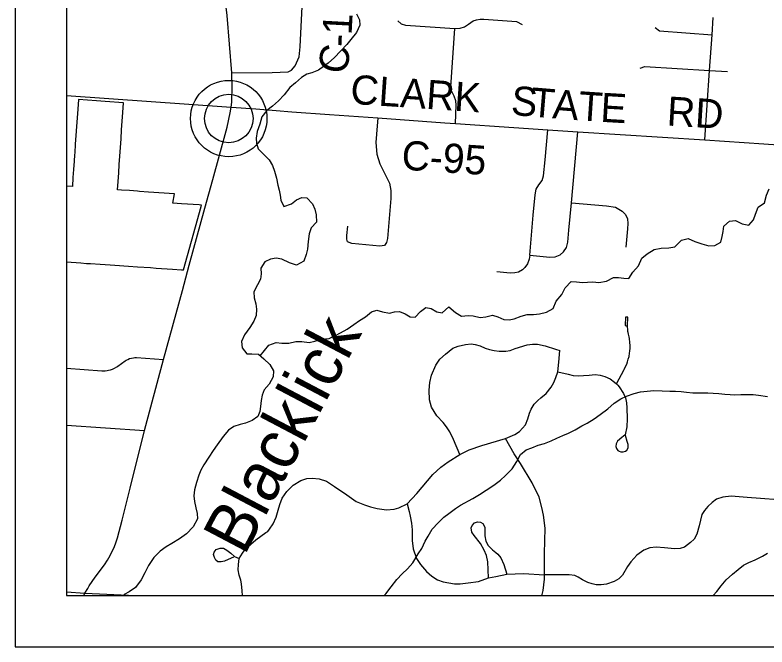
# Model space of a CAD drawing. Extents: x 0 to 91.3, y -0.7 to 22.
# Drawn here: x 2 to 3.464, y 14 to 15.231 of the extents above; entities that cross this region are included whole.
import ezdxf

# ---------------------------------------------------------------- set-up
doc = ezdxf.new("R2010")
doc.units = 0
for name, color, linetype in [('GM_X_Corporation', 7, 'Continuous'), ('GM_X_County_Road', 7, 'Continuous'), ('GM_X_County_Road_Text', 7, 'Continuous'), ('GM_X_Minor_River', 7, 'Continuous'), ('GM_X_Minor_River_Text', 7, 'Continuous'), ('GM_X_Township_Road', 7, 'Continuous'), ('GM_X_Unincorporated', 7, 'Continuous'), ('GM_X_Unincorporated_Location', 7, 'Continuous'), ('SH_Data', 7, 'Continuous')]:
    doc.layers.add(name, color=color, linetype=linetype)

msp = doc.modelspace()

# ---------------------------------------------------------------- linework, layer by layer
at = {"layer": 'GM_X_Corporation'}
msp.add_lwpolyline([(2.1, 20.8844), (2.1, 14.1), (4.5273, 14.1), (4.5361, 14.2234), (4.5616, 14.5843), (4.5901, 15.0403), (4.6027, 15.2253), (4.6241, 15.5494), (4.624, 15.5538), (4.6966, 16.7952), (4.7039, 16.921), (4.7369, 17.4842), (4.7381, 17.5094), (4.7391, 17.5254), (4.7562, 17.8002), (4.7688, 17.9561), (4.7799, 18.0944), (4.7833, 18.1361), (4.8242, 18.6326)], dxfattribs=at)
for points in [[(2.1, 15.7138), (2.1, 14.1), (4.5273, 14.1), (4.5361, 14.2234), (4.5616, 14.5843), (4.5901, 15.0403), (4.6027, 15.2253), (4.6241, 15.5494), (4.1118, 15.5861), (3.7652, 15.6088), (3.1007, 15.6507), (2.7426, 15.6727), (2.3611, 15.6969)], [(2.1, 14.8978), (2.1, 14.7499), (2.1282, 14.748), (2.1393, 14.7473), (2.1471, 14.7468), (2.166, 14.7455), (2.1849, 14.7442), (2.1944, 14.7436), (2.2208, 14.7418), (2.2386, 14.7406), (2.2637, 14.7389), (2.275, 14.7382), (2.3068, 14.736), (2.3242, 14.7349), (2.3281, 14.7346), (2.359, 14.8462), (2.3629, 14.8607), (2.3587, 14.861), (2.3239, 14.8634), (2.3072, 14.8645), (2.3102, 14.8825), (2.2599, 14.8862), (2.2423, 14.8875), (2.2386, 14.8877), (2.223, 14.8889), (2.2072, 14.89), (2.1994, 14.8906), (2.2006, 14.9069), (2.2017, 14.9239), (2.2029, 14.94), (2.204, 14.956), (2.2051, 14.973), (2.2063, 14.99), (2.2075, 15.0071), (2.2086, 15.0241), (2.2098, 15.0411), (2.2111, 15.06), (2.1757, 15.0626), (2.1587, 15.0639), (2.1233, 15.0665), (2.122, 15.0476), (2.1208, 15.0306), (2.1197, 15.0136), (2.1185, 14.9966), (2.1173, 14.9796), (2.1161, 14.9626), (2.1159, 14.9587), (2.115, 14.9465), (2.1139, 14.9304), (2.1128, 14.9144), (2.1116, 14.8969)]]:
    msp.add_lwpolyline(points, close=True, dxfattribs=at)
at = {"layer": 'GM_X_County_Road'}
msp.add_line((2.1, 15.0745), (2.4208, 15.0514), dxfattribs=at)
for points in [[(2.4217, 15.1187), (2.413, 15.2298), (2.3896, 15.4238), (2.3677, 15.6299), (2.3614, 15.6963)], [(2.4217, 15.1187), (2.5005, 15.1191), (2.5317, 15.1201), (2.5384, 15.1237), (2.5452, 15.1323), (2.5529, 15.1498), (2.5547, 15.1688), (2.5697, 15.4694)], [(2.4208, 15.0514), (2.4219, 15.0611), (2.4221, 15.0671), (2.4229, 15.088), (2.4217, 15.1187)], [(2.2522, 14.4216), (2.2887, 14.5597), (2.3258, 14.6947), (2.3388, 14.7436), (2.3695, 14.8547), (2.3849, 14.9109), (2.4127, 15.0126), (2.4189, 15.0403), (2.4208, 15.0514)], [(2.4208, 15.0514), (2.4687, 15.048), (2.508, 15.0447), (2.5387, 15.0425)], [(2.5387, 15.0425), (2.6121, 15.0373), (2.706, 15.0307), (2.8364, 15.0213), (2.8571, 15.0199), (2.971, 15.012), (3.0369, 15.0072), (3.0952, 15.0032), (3.3423, 14.9878), (3.4576, 14.9802), (3.5594, 14.9727)], [(2.1341, 14.1), (2.1361, 14.1049), (2.1414, 14.114), (2.1444, 14.1191), (2.1501, 14.1278), (2.156, 14.1357), (2.174, 14.16), (2.1802, 14.1694), (2.1851, 14.1781), (2.1934, 14.1954), (2.1963, 14.2029), (2.1994, 14.2127), (2.2086, 14.2467), (2.2241, 14.3094), (2.2522, 14.4216)]]:
    msp.add_lwpolyline(points, dxfattribs=at)
at = {"layer": 'GM_X_Minor_River'}
for points in [[(2.6645, 15.2332), (2.6705, 15.2218), (2.6708, 15.2115), (2.6647, 15.1971), (2.6536, 15.1835), (2.6455, 15.1733), (2.6333, 15.1609), (2.6215, 15.1484), (2.6096, 15.1375), (2.6001, 15.1307), (2.5906, 15.1236), (2.5776, 15.1187), (2.5677, 15.1161), (2.5575, 15.1094), (2.5456, 15.0988), (2.5349, 15.0901), (2.5235, 15.0754), (2.5128, 15.0641), (2.5013, 15.0535), (2.4903, 15.0449), (2.4803, 15.0328), (2.4764, 15.0184), (2.4714, 15.0044), (2.4694, 14.9911), (2.4701, 14.9816), (2.4735, 14.9706), (2.4821, 14.961), (2.4946, 14.9488), (2.5013, 14.9378), (2.5051, 14.9267), (2.5092, 14.9131), (2.5117, 14.8994), (2.514, 14.8895), (2.5158, 14.88), (2.5176, 14.8701), (2.5232, 14.8579), (2.5381, 14.8635), (2.5476, 14.8707), (2.5579, 14.8756), (2.5678, 14.8751), (2.5791, 14.8633), (2.5832, 14.8526), (2.5858, 14.842), (2.5868, 14.8276), (2.5765, 14.8166), (2.5726, 14.8049), (2.5703, 14.7897), (2.569, 14.7749), (2.5667, 14.7643), (2.562, 14.7514), (2.548, 14.7439), (2.5343, 14.7482), (2.5196, 14.7551), (2.5082, 14.7571), (2.4972, 14.7552), (2.4865, 14.75), (2.4785, 14.7379), (2.4788, 14.7269), (2.4779, 14.7163), (2.4718, 14.7057), (2.4645, 14.6921), (2.4656, 14.6799), (2.4685, 14.6685)], [(2.4771, 14.5674), (2.4942, 14.5879), (2.5083, 14.5928), (2.5193, 14.5919), (2.533, 14.5918), (2.5467, 14.5952), (2.558, 14.5951), (2.5728, 14.5931), (2.5838, 14.5957), (2.5964, 14.5994), (2.6112, 14.6012), (2.6238, 14.6065), (2.6337, 14.6117), (2.6462, 14.6192), (2.6592, 14.6279), (2.6706, 14.6358), (2.6824, 14.6429), (2.6935, 14.6527), (2.7042, 14.6561), (2.7155, 14.653), (2.7288, 14.6502), (2.7383, 14.6528), (2.7486, 14.6532), (2.7592, 14.6489), (2.769, 14.6428), (2.7785, 14.6424), (2.7892, 14.6533), (2.7995, 14.6612), (2.8097, 14.6596), (2.821, 14.6527), (2.8313, 14.6508), (2.8443, 14.6625), (2.8571, 14.6518), (2.8692, 14.6445), (2.8821, 14.6455), (2.8916, 14.6451), (2.9052, 14.642), (2.9162, 14.6434), (2.9292, 14.6464), (2.9394, 14.6433), (2.9511, 14.6379), (2.9618, 14.6371), (2.9713, 14.6389), (2.9853, 14.6442), (2.9971, 14.6475), (3.0093, 14.6478), (3.021, 14.6489), (3.0347, 14.6522), (3.0473, 14.6593), (3.0531, 14.6733), (3.0645, 14.6866), (3.0707, 14.6994), (3.0822, 14.7119), (3.0928, 14.7114), (3.1042, 14.7102), (3.1144, 14.7109), (3.1243, 14.7112), (3.1364, 14.71), (3.1512, 14.7126), (3.1646, 14.7197), (3.1748, 14.7197), (3.1847, 14.7181), (3.1945, 14.7177), (3.2026, 14.7301), (3.2133, 14.7426), (3.2202, 14.7574), (3.2301, 14.7656), (3.2442, 14.7743), (3.2579, 14.7769), (3.2727, 14.7775), (3.2841, 14.7797), (3.2975, 14.7922), (3.3104, 14.7955), (3.3233, 14.7898), (3.3365, 14.7851), (3.3502, 14.7816), (3.3619, 14.7823), (3.3737, 14.7883), (3.3765, 14.7993), (3.378, 14.8095), (3.3796, 14.8194), (3.3903, 14.8292), (3.4021, 14.8307), (3.4153, 14.8245), (3.4282, 14.8214), (3.4374, 14.8323), (3.4409, 14.8429), (3.4463, 14.8566), (3.4585, 14.8652), (3.4624, 14.8804), (3.4681, 14.8925)], [(2.4685, 14.6685), (2.47, 14.6583), (2.4692, 14.6454), (2.4645, 14.6344), (2.4569, 14.6223), (2.4469, 14.6083), (2.4408, 14.5951), (2.4418, 14.5825), (2.4512, 14.5707), (2.4607, 14.5707), (2.474, 14.5702), (2.4842, 14.561), (2.4959, 14.5503), (2.503, 14.5378), (2.5026, 14.526), (2.4945, 14.512), (2.485, 14.5007), (2.4807, 14.4908), (2.4791, 14.4798), (2.4775, 14.4685), (2.4763, 14.459), (2.4725, 14.4491), (2.4614, 14.4412), (2.4485, 14.436), (2.4382, 14.4334), (2.4261, 14.4293), (2.4158, 14.4225), (2.4051, 14.4097), (2.3936, 14.3935), (2.3859, 14.3829), (2.3771, 14.37), (2.3675, 14.3545), (2.3618, 14.3443), (2.3575, 14.3345), (2.3529, 14.3201), (2.3494, 14.3061), (2.3482, 14.2947), (2.3492, 14.2833), (2.3518, 14.2711), (2.3548, 14.2597), (2.3551, 14.2499), (2.3466, 14.234), (2.334, 14.2204), (2.3199, 14.2106), (2.3051, 14.2016), (2.2944, 14.1948), (2.2826, 14.1865), (2.27, 14.1745), (2.2596, 14.1586), (2.2527, 14.1442), (2.2454, 14.1306), (2.2347, 14.1159), (2.2221, 14.1072), (2.2126, 14.102), (2.2116, 14.1)], [(2.7187, 14.1), (2.722, 14.1034), (2.7319, 14.117), (2.743, 14.1314), (2.7533, 14.1427), (2.764, 14.1521), (2.7743, 14.1638), (2.7847, 14.1816), (2.792, 14.1918), (2.7981, 14.2058), (2.8039, 14.2156), (2.8119, 14.2293), (2.8234, 14.2421), (2.8345, 14.2527), (2.8444, 14.2602), (2.857, 14.27), (2.8669, 14.276), (2.8913, 14.2895), (2.9042, 14.297), (2.9172, 14.3053), (2.9317, 14.3151), (2.9446, 14.3252), (2.9545, 14.3339), (2.9679, 14.3471), (2.9767, 14.3611), (2.984, 14.3751), (2.9951, 14.3838), (3.0061, 14.3882), (3.0183, 14.3931), (3.0308, 14.3961), (3.0434, 14.4013), (3.0544, 14.4065), (3.0659, 14.4118), (3.0773, 14.4167), (3.0902, 14.423), (3.1032, 14.4309), (3.1135, 14.4362), (3.1275, 14.4444), (3.139, 14.4527), (3.1539, 14.464), (3.1664, 14.4746), (3.1794, 14.4832), (3.1904, 14.4885), (3.2053, 14.4937), (3.2174, 14.4967), (3.2304, 14.4981), (3.2436, 14.4995), (3.2596, 14.4991)], [(3.2596, 14.4991), (3.2748, 14.4986), (3.2854, 14.4981), (3.2968, 14.4977), (3.3066, 14.4965), (3.3195, 14.4953), (3.329, 14.4948), (3.3389, 14.4952), (3.3484, 14.4951), (3.3586, 14.4947), (3.3696, 14.4938), (3.3818, 14.4923), (3.3916, 14.4918), (3.4011, 14.4914), (3.4129, 14.4917), (3.4239, 14.492), (3.4368, 14.4915), (3.447, 14.4907), (3.4645, 14.488)], [(3.3585, 14.1), (3.3657, 14.1083), (3.3745, 14.1192), (3.3844, 14.1306), (3.3966, 14.1415), (3.4073, 14.1506), (3.4176, 14.1592), (3.4283, 14.1645), (3.4408, 14.1697), (3.4549, 14.1772), (3.4645, 14.1825)]]:
    msp.add_lwpolyline(points, dxfattribs=at)
at = {"layer": 'GM_X_Township_Road'}
for p, q in [((3.3516, 15.1232), (3.387, 15.1209)), ((2.1, 14.4321), (2.2522, 14.4216)), ((2.1, 14.1072), (2.1361, 14.1049)), ((2.1361, 14.1049), (2.2351, 14.1))]:
    msp.add_line(p, q, dxfattribs=at)
for points in [[(2.856, 15.2048), (2.8661, 15.2051), (2.8746, 15.2079), (2.8829, 15.213), (2.8919, 15.2194), (2.8985, 15.2217), (2.905, 15.2227), (2.9126, 15.2227), (2.9761, 15.2186), (2.9872, 15.2127)], [(3.3423, 14.9878), (3.3516, 15.1232), (3.3568, 15.1925), (3.3586, 15.2262)], [(2.7448, 15.2197), (2.7513, 15.2138), (2.7602, 15.2112), (2.856, 15.2048)], [(3.246, 15.2067), (3.2545, 15.2003), (3.3568, 15.1925)], [(2.8571, 15.0199), (2.8588, 15.0557), (2.8579, 15.0639), (2.8546, 15.0731), (2.8493, 15.0836), (2.8483, 15.0908), (2.856, 15.2048)], [(3.2167, 15.1276), (3.2256, 15.1309), (3.3516, 15.1232)], [(2.706, 15.0307), (2.7038, 14.999), (2.7025, 14.9827), (2.7043, 14.96), (2.7103, 14.9414), (2.7289, 14.9037), (2.7312, 14.8889), (2.7316, 14.8734), (2.7251, 14.7955), (2.7231, 14.7879), (2.719, 14.7823), (2.7101, 14.7807), (2.6557, 14.7858), (2.6472, 14.7895), (2.6459, 14.7946), (2.6459, 14.8014), (2.6478, 14.82)], [(3.0019, 14.7629), (3.0087, 14.8409), (3.0121, 14.8805), (3.0142, 14.8918), (3.0194, 14.9005), (3.0257, 14.9085), (3.0287, 14.9178), (3.0316, 14.9489), (3.0369, 15.0072)], [(3.0019, 14.7629), (3.0407, 14.7591), (3.0511, 14.7598), (3.0611, 14.764), (3.0676, 14.7694), (3.0734, 14.7782), (3.0762, 14.7886), (3.078, 14.812), (3.0831, 14.8651), (3.0952, 15.0032)], [(3.0831, 14.8651), (3.151, 14.859), (3.1687, 14.8565), (3.1817, 14.8492), (3.1885, 14.8423), (3.1918, 14.834), (3.1927, 14.8251), (3.1922, 14.8146), (3.1889, 14.7785)], [(3.0019, 14.7629), (3.0007, 14.7552), (2.9976, 14.7462), (2.9925, 14.7389), (2.9879, 14.7344), (2.9799, 14.7303), (2.9727, 14.7287), (2.9635, 14.7284), (2.938, 14.7306)], [(3.1707, 14.5123), (3.1856, 14.5402), (3.1864, 14.5419), (3.1885, 14.5461), (3.1906, 14.551), (3.1922, 14.5556), (3.1937, 14.5605), (3.195, 14.5657), (3.1961, 14.5722), (3.1966, 14.5764), (3.197, 14.5822), (3.197, 14.5882), (3.1967, 14.5927), (3.1965, 14.5955), (3.1961, 14.5986), (3.1957, 14.6012), (3.1951, 14.6041), (3.1945, 14.6069), (3.194, 14.609), (3.1933, 14.6125), (3.1929, 14.6148), (3.1926, 14.6173), (3.1925, 14.6198), (3.1924, 14.6222), (3.1924, 14.6256), (3.1926, 14.6422), (3.1879, 14.6422), (3.1877, 14.627), (3.1893, 14.6256), (3.1918, 14.6256)], [(2.4428, 14.1), (2.4422, 14.1095), (2.4411, 14.1229), (2.4396, 14.13), (2.4361, 14.1396), (2.4343, 14.1502), (2.4348, 14.1604), (2.4361, 14.1726), (2.4427, 14.1828), (2.4494, 14.1916), (2.4689, 14.2086), (2.4881, 14.2227), (2.4919, 14.2252), (2.4955, 14.2297), (2.5021, 14.2396), (2.5084, 14.2526), (2.5122, 14.2665), (2.5153, 14.2774), (2.5202, 14.2897), (2.529, 14.3031), (2.5413, 14.3154), (2.5564, 14.3244), (2.5682, 14.3279), (2.5781, 14.329), (2.592, 14.3273), (2.6059, 14.3231), (2.6219, 14.3125), (2.6455, 14.2965), (2.6639, 14.2833), (2.6804, 14.2768), (2.6917, 14.273), (2.705, 14.2696), (2.7227, 14.2673), (2.7377, 14.2684), (2.7472, 14.2713), (2.7634, 14.2787), (2.7822, 14.2989), (2.8132, 14.3357), (2.8288, 14.3505), (2.843, 14.3609), (2.8657, 14.3746), (2.8839, 14.3838), (2.9086, 14.3922), (2.9544, 14.4059), (2.9729, 14.4142), (2.9816, 14.4197), (2.9936, 14.4326), (2.9983, 14.4444), (3.0011, 14.4554), (3.0043, 14.4634), (3.0106, 14.4727), (3.0174, 14.48), (3.0237, 14.4851), (3.034, 14.4936), (3.0432, 14.5062), (3.0485, 14.5153), (3.0526, 14.5246), (3.0564, 14.5358), (3.0587, 14.5547), (3.0604, 14.5775)], [(2.8657, 14.3746), (2.8535, 14.4044), (2.8462, 14.419), (2.8396, 14.4285), (2.8335, 14.4371), (2.8208, 14.4501), (2.8109, 14.4671), (2.8066, 14.4815), (2.8061, 14.5002), (2.8072, 14.5151), (2.8105, 14.5295), (2.819, 14.5488), (2.827, 14.5609), (2.8378, 14.5703), (2.8524, 14.5819), (2.8628, 14.5859), (2.8767, 14.5893), (2.8875, 14.5903), (2.8956, 14.5894), (2.9053, 14.5864), (2.9152, 14.5819), (2.9233, 14.5792), (2.9328, 14.5772), (2.942, 14.576), (2.955, 14.5763), (2.9634, 14.5776), (2.9734, 14.5813), (2.9967, 14.5887), (3.007, 14.5899), (3.0172, 14.5899), (3.0321, 14.5869), (3.0521, 14.5798), (3.0604, 14.5775)], [(2.1, 14.5431), (2.1688, 14.5377), (2.1719, 14.5376), (2.1753, 14.5378), (2.1791, 14.5383), (2.1822, 14.5389), (2.1857, 14.5399), (2.1897, 14.5414), (2.1938, 14.5434), (2.198, 14.5459), (2.2, 14.5473), (2.2144, 14.5575), (2.2166, 14.5588), (2.2197, 14.5603), (2.2229, 14.5616), (2.2269, 14.5627), (2.2306, 14.5634), (2.2334, 14.5636), (2.2367, 14.5636), (2.2887, 14.5597)], [(3.0564, 14.5358), (3.0764, 14.5312), (3.0865, 14.5287), (3.0966, 14.5284), (3.1067, 14.5289), (3.1174, 14.5297), (3.1293, 14.5307), (3.1386, 14.5292), (3.1477, 14.5267), (3.1581, 14.5221), (3.167, 14.5158), (3.1707, 14.5123), (3.1733, 14.5098), (3.176, 14.5066), (3.1844, 14.4938), (3.1879, 14.4851), (3.1899, 14.4755), (3.1911, 14.4656), (3.1913, 14.4443), (3.1905, 14.4291), (3.1876, 14.4134), (3.1809, 14.4081), (3.1728, 14.4006), (3.1697, 14.3954), (3.1692, 14.3902), (3.1706, 14.3867), (3.1734, 14.3826), (3.1759, 14.3811), (3.179, 14.3801), (3.1834, 14.3801), (3.1883, 14.3812), (3.191, 14.3832), (3.1935, 14.388), (3.1935, 14.3945), (3.1914, 14.4004), (3.1879, 14.4117)], [(3.0304, 14.1502), (3.0307, 14.1823), (3.0316, 14.2312), (3.0287, 14.2566), (3.0255, 14.2716), (3.0199, 14.2915), (3.0065, 14.3198), (2.984, 14.3577), (2.9715, 14.3762), (2.9544, 14.4059)], [(3.5113, 14.2849), (3.425, 14.2913), (3.3939, 14.2936), (3.3779, 14.2921), (3.3652, 14.2877), (3.3569, 14.2812), (3.3486, 14.2735), (3.3417, 14.2661), (3.337, 14.2578), (3.3317, 14.2361), (3.3272, 14.2195), (3.3219, 14.21), (3.3144, 14.2032), (3.3029, 14.1943), (3.2949, 14.1916), (3.2837, 14.1911), (3.2641, 14.1934), (3.2478, 14.1943), (3.2357, 14.193), (3.2237, 14.1888), (3.21, 14.1787), (3.1986, 14.166), (3.1924, 14.1565), (3.1823, 14.1399), (3.1751, 14.1327), (3.166, 14.1278), (3.1515, 14.1223), (3.141, 14.121), (3.1309, 14.1208), (3.1232, 14.1231), (3.1147, 14.1257), (3.1044, 14.1309), (3.0959, 14.136), (3.0895, 14.1394), (3.0786, 14.1406), (3.0303, 14.1404)], [(2.7634, 14.2787), (2.7674, 14.264), (2.7693, 14.2549), (2.7714, 14.2412), (2.7729, 14.2279), (2.7731, 14.2071), (2.7752, 14.1912), (2.7812, 14.1726), (2.7891, 14.1605), (2.8008, 14.1467), (2.811, 14.138), (2.8224, 14.1311), (2.8335, 14.1272), (2.8552, 14.123), (2.8663, 14.1233), (2.8822, 14.1248), (2.9023, 14.1278), (2.9213, 14.1344), (2.9357, 14.1374), (2.9569, 14.1417), (2.9894, 14.1429), (3.0303, 14.1404)], [(2.9213, 14.1344), (2.9204, 14.1659), (2.9177, 14.178), (2.9131, 14.1885), (2.9059, 14.2014), (2.8939, 14.2173), (2.8888, 14.2237), (2.8876, 14.2318), (2.89, 14.2369), (2.8945, 14.2417), (2.9002, 14.2438), (2.9062, 14.2429), (2.9104, 14.2402), (2.9146, 14.2336), (2.9143, 14.2267), (2.9143, 14.2167), (2.9164, 14.2059), (2.9207, 14.1978), (2.9291, 14.1891), (2.936, 14.184), (2.9399, 14.1805), (2.9454, 14.1736), (2.9515, 14.1607), (2.9569, 14.1417)], [(2.4253, 14.1747), (2.4151, 14.1703), (2.4077, 14.167), (2.4009, 14.166), (2.395, 14.1661), (2.3905, 14.1694), (2.388, 14.174), (2.3866, 14.1801), (2.3873, 14.1848), (2.3914, 14.19), (2.399, 14.1925), (2.406, 14.1923), (2.4124, 14.1886), (2.4203, 14.1826), (2.4273, 14.176), (2.4361, 14.1726)], [(3.0252, 14.1), (3.0262, 14.1022), (3.028, 14.1097), (3.0303, 14.1319), (3.0303, 14.1404), (3.0304, 14.1502)]]:
    msp.add_lwpolyline(points, dxfattribs=at)
at = {"layer": 'GM_X_Unincorporated'}
for radius in [0.0744, 0.0472]:
    msp.add_circle((2.416, 15.0293), radius, dxfattribs=at)
at = {"layer": 'GM_X_Unincorporated_Location'}
msp.add_line((2.416, 15.0293), (2.416, 15.0293), dxfattribs=at)
at = {"layer": 'SH_Data'}
for p, q in [((2, 21), (2, 14)), ((2.1, 20.9), (2.1, 14.1)), ((2.1, 14.1), (8.9, 14.1)), ((2.1, 14.1), (2.1, 14.1)), ((2, 14), (9, 14))]:
    msp.add_line(p, q, dxfattribs=at)

# ---------------------------------------------------------------- texts
at = {"layer": 'GM_X_County_Road_Text'}
for s, height, rotation, p in [('1', 0.0568, 86.8969, (2.6549, 15.1911)), ('-', 0.0568, 87.3684, (2.6539, 15.1679)), ('C', 0.0568, 79.3499, (2.6442, 15.1135)), ('CLARK', 0.05682, 356.1481, (2.6515, 15.0583)), ('S', 0.0568, 355.2671, (2.964, 15.0367)), ('T', 0.0568, 355.2677, (3.0022, 15.0335)), ('A', 0.0568, 355.4806, (3.0448, 15.03)), ('T', 0.0568, 356.1624, (3.0953, 15.026)), ('E', 0.0568, 356.647, (3.1383, 15.0231)), ('RD', 0.05682, 356.5449, (3.2676, 15.0158)), ('C-95', 0.05682, 356.2309, (2.7511, 14.9301))]:
    msp.add_text(s, height=height, rotation=rotation, dxfattribs=at).set_placement(p)
at = {"layer": 'GM_X_Minor_River_Text'}
msp.add_text('Blacklick', height=0.09469, rotation=62.1927, dxfattribs=at).set_placement((2.4462, 14.1759))

doc.saveas('drawing.dxf')
